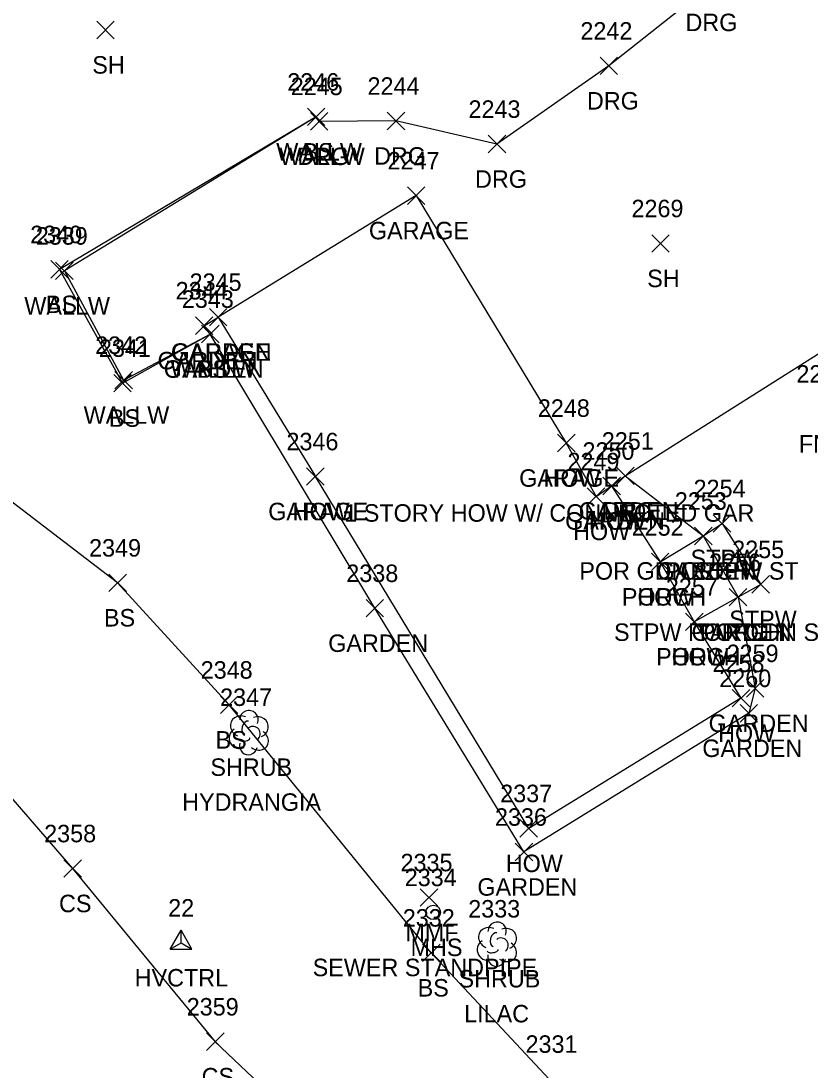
# Model space of a CAD drawing. Extents: x 1520648 to 1523413, y 732854 to 735518.
# Drawn here: x 1521973.9 to 1522064.2, y 733841.6 to 733961.6 of the extents above; entities that cross this region are included whole.
import ezdxf

# ---------------------------------------------------------------- set-up
doc = ezdxf.new("R2010")
doc.units = 0
for name, color, linetype in [('C_A', 7, 'Continuous'), ('C_I', 7, 'Continuous'), ('CPSM', 7, 'Continuous'), ('L_A', 7, 'Continuous'), ('L_C', 7, 'Continuous'), ('L_I', 7, 'Continuous'), ('L_TIC', 7, 'Continuous'), ('LAPB', 7, 'Continuous'), ('LBC', 7, 'Continuous'), ('LBF', 7, 'Continuous'), ('LELB', 7, 'Continuous'), ('LSH', 7, 'Continuous'), ('LW', 7, 'Continuous'), ('R_A', 7, 'Continuous'), ('R_I', 7, 'Continuous'), ('R_TIC', 7, 'Continuous'), ('RDG', 7, 'Continuous'), ('U_A', 7, 'Continuous'), ('U_I', 7, 'Continuous'), ('USMH', 7, 'Continuous')]:
    doc.layers.add(name, color=color, linetype=linetype)

msp = doc.modelspace()

# ---------------------------------------------------------------- linework, layer by layer
at = {"layer": 'CPSM'}
for p, q in [((1521990.97, 733855.4), (1521992.22, 733857.56)), ((1521993.47, 733855.4), (1521992.22, 733857.56)), ((1521992.22, 733856.12), (1521992.22, 733857.56)), ((1521990.97, 733855.4), (1521992.22, 733856.12)), ((1521990.97, 733855.4), (1521993.47, 733855.4)), ((1521992.22, 733856.12), (1521992.22, 733856.12)), ((1521992.22, 733856.12), (1521993.47, 733855.4))]:
    msp.add_line(p, q, dxfattribs=at)
at = {"layer": 'L_TIC'}
for points in [[(1521982.57, 733959.57), (1521984.57, 733961.57)], [(1521984.57, 733959.57), (1521982.57, 733961.57)], [(1522006.7, 733949.62), (1522008.7, 733951.62)], [(1522008.7, 733949.62), (1522006.7, 733951.62)], [(1522006.7, 733949.62), (1522008.7, 733951.62)], [(1522008.7, 733949.62), (1522006.7, 733951.62)], [(1522007.04, 733949.11), (1522009.04, 733951.11)], [(1522009.04, 733949.11), (1522007.04, 733951.11)], [(1522018.13, 733940.61), (1522020.13, 733942.61)], [(1522020.13, 733940.61), (1522018.13, 733942.61)], [(1522018.13, 733940.61), (1522020.13, 733942.61)], [(1522020.13, 733940.61), (1522018.13, 733942.61)], [(1522046.11, 733935.14), (1522048.11, 733937.14)], [(1522048.11, 733935.14), (1522046.11, 733937.14)], [(1521977.3, 733932.17), (1521979.3, 733934.17)], [(1521979.3, 733932.17), (1521977.3, 733934.17)], [(1521977.86, 733932), (1521979.86, 733934)], [(1521979.86, 733932), (1521977.86, 733934)], [(1521995.46, 733926.71), (1521997.46, 733928.71)], [(1521997.46, 733926.71), (1521995.46, 733928.71)], [(1521995.46, 733926.71), (1521997.46, 733928.71)], [(1521997.46, 733926.71), (1521995.46, 733928.71)], [(1521993.86, 733925.73), (1521995.86, 733927.73)], [(1521995.86, 733925.73), (1521993.86, 733927.73)], [(1521994.57, 733924.77), (1521996.57, 733926.77)], [(1521996.57, 733924.77), (1521994.57, 733926.77)], [(1521994.57, 733924.77), (1521996.57, 733926.77)], [(1521996.57, 733924.77), (1521994.57, 733926.77)], [(1521994.57, 733924.77), (1521996.57, 733926.77)], [(1521996.57, 733924.77), (1521994.57, 733926.77)], [(1521984.65, 733919.5), (1521986.65, 733921.5)], [(1521986.65, 733919.5), (1521984.65, 733921.5)], [(1521984.51, 733919.16), (1521986.51, 733921.16)], [(1521986.51, 733919.16), (1521984.51, 733921.16)], [(1522035.33, 733912.3), (1522037.33, 733914.3)], [(1522037.33, 733912.3), (1522035.33, 733914.3)], [(1522035.33, 733912.3), (1522037.33, 733914.3)], [(1522037.33, 733912.3), (1522035.33, 733914.3)], [(1522042.08, 733908.54), (1522044.08, 733910.54)], [(1522044.08, 733908.54), (1522042.08, 733910.54)], [(1522006.6, 733908.47), (1522008.6, 733910.47)], [(1522008.6, 733908.47), (1522006.6, 733910.47)], [(1522006.6, 733908.47), (1522008.6, 733910.47)], [(1522008.6, 733908.47), (1522006.6, 733910.47)], [(1522040.52, 733907.39), (1522042.52, 733909.39)], [(1522042.52, 733907.39), (1522040.52, 733909.39)], [(1522040.52, 733907.39), (1522042.52, 733909.39)], [(1522042.52, 733907.39), (1522040.52, 733909.39)], [(1522038.73, 733906.19), (1522040.73, 733908.19)], [(1522040.73, 733906.19), (1522038.73, 733908.19)], [(1522053.16, 733903.1), (1522055.16, 733905.1)], [(1522055.16, 733903.1), (1522053.16, 733905.1)], [(1522051.01, 733901.67), (1522053.01, 733903.67)], [(1522053.01, 733901.67), (1522051.01, 733903.67)], [(1522051.01, 733901.67), (1522053.01, 733903.67)], [(1522053.01, 733901.67), (1522051.01, 733903.67)], [(1522051.01, 733901.67), (1522053.01, 733903.67)], [(1522053.01, 733901.67), (1522051.01, 733903.67)], [(1522046.07, 733898.7), (1522048.07, 733900.7)], [(1522048.07, 733898.7), (1522046.07, 733900.7)], [(1522046.07, 733898.7), (1522048.07, 733900.7)], [(1522048.07, 733898.7), (1522046.07, 733900.7)], [(1521983.96, 733896.31), (1521985.96, 733898.31)], [(1521985.96, 733896.31), (1521983.96, 733898.31)], [(1522057.58, 733896.13), (1522059.58, 733898.13)], [(1522059.58, 733896.13), (1522057.58, 733898.13)], [(1522054.99, 733894.66), (1522056.99, 733896.66)], [(1522056.99, 733894.66), (1522054.99, 733896.66)], [(1522054.99, 733894.66), (1522056.99, 733896.66)], [(1522056.99, 733894.66), (1522054.99, 733896.66)], [(1522054.99, 733894.66), (1522056.99, 733896.66)], [(1522056.99, 733894.66), (1522054.99, 733896.66)], [(1522013.4, 733893.4), (1522015.4, 733895.4)], [(1522015.4, 733893.4), (1522013.4, 733895.4)], [(1522049.98, 733891.85), (1522051.98, 733893.85)], [(1522051.98, 733891.85), (1522049.98, 733893.85)], [(1522049.98, 733891.85), (1522051.98, 733893.85)], [(1522051.98, 733891.85), (1522049.98, 733893.85)], [(1522056.95, 733884.24), (1522058.95, 733886.24)], [(1522058.95, 733884.24), (1522056.95, 733886.24)], [(1521996.73, 733882.34), (1521998.73, 733884.34)], [(1521998.73, 733882.34), (1521996.73, 733884.34)], [(1522055.32, 733883.1), (1522057.32, 733885.1)], [(1522057.32, 733883.1), (1522055.32, 733885.1)], [(1522056.23, 733881.38), (1522058.23, 733883.38)], [(1522058.23, 733881.38), (1522056.23, 733883.38)], [(1522031.02, 733868.21), (1522033.02, 733870.21)], [(1522033.02, 733868.21), (1522031.02, 733870.21)], [(1522030.48, 733865.51), (1522032.48, 733867.51)], [(1522032.48, 733865.51), (1522030.48, 733867.51)], [(1521978.81, 733863.62), (1521980.81, 733865.62)], [(1521980.81, 733863.62), (1521978.81, 733865.62)], [(1522019.61, 733860.3), (1522021.61, 733862.3)], [(1522021.61, 733860.3), (1522019.61, 733862.3)], [(1522019.87, 733853.97), (1522021.87, 733855.97)], [(1522021.87, 733853.97), (1522019.87, 733855.97)], [(1521995.14, 733843.8), (1521997.14, 733845.8)], [(1521997.14, 733843.8), (1521995.14, 733845.8)]]:
    msp.add_lwpolyline(points, dxfattribs=at)
at = {"layer": 'LAPB'}
for points in [[(1522055.99, 733895.66), (1522057.95, 733885.24), (1522057.23, 733882.38), (1522031.48, 733866.51), (1522014.4, 733894.4), (1521995.57, 733925.77), (1521994.86, 733926.73), (1521996.46, 733927.71)], [(1522041.52, 733908.39), (1522043.08, 733909.54), (1522052.01, 733902.67)]]:
    msp.add_lwpolyline(points, dxfattribs=at)
at = {"layer": 'LBC'}
for points in [[(1522019.13, 733941.61), (1521996.46, 733927.71), (1522007.6, 733909.47)], [(1522019.13, 733941.61), (1522036.33, 733913.3)], [(1522036.33, 733913.3), (1522039.73, 733907.19), (1522041.52, 733908.39), (1522047.07, 733899.7), (1522050.98, 733892.85), (1522056.32, 733884.1), (1522032.02, 733869.21), (1522007.6, 733909.47)]]:
    msp.add_lwpolyline(points, dxfattribs=at)
at = {"layer": 'LBF'}
for points in [[(1522052.01, 733902.67), (1522054.16, 733904.1), (1522058.58, 733897.13), (1522055.99, 733895.66)], [(1522047.07, 733899.7), (1522052.01, 733902.67), (1522055.99, 733895.66), (1522050.98, 733892.85)]]:
    msp.add_lwpolyline(points, dxfattribs=at)
at = {"layer": 'LELB'}
for points in [[(1522007.7, 733950.62), (1521978.3, 733933.17), (1521985.51, 733920.16), (1521995.57, 733925.77)], [(1522038.26, 733821.74), (1522034.35, 733840.53), (1522020.87, 733854.97), (1521997.73, 733883.34), (1521984.96, 733897.31), (1521967.97, 733910.29), (1521948.34, 733926.34)], [(1521935.5, 733911.29), (1521950.9, 733894.84), (1521962.92, 733884.06), (1521979.81, 733864.62), (1521996.14, 733844.8), (1522019.29, 733822.84), (1522000.66, 733804.64), (1521971.81, 733783.01), (1521953.74, 733771.36), (1521896.07, 733749.17)]]:
    msp.add_lwpolyline(points, dxfattribs=at)
at = {"layer": 'LSH'}
for p, q in [((1521999.95, 733880.22), (1521999.95, 733880.22)), ((1521999.95, 733880.22), (1521999.95, 733880.22)), ((1522028.36, 733856.01), (1522028.36, 733856.01)), ((1522028.36, 733856.01), (1522028.36, 733856.01))]:
    msp.add_line(p, q, dxfattribs=at)
for centre in [(1522000, 733881.65), (1522028.41, 733857.44)]:
    msp.add_arc(centre, 1.05, 335.5272, 180.9563, dxfattribs=at)
for centre, major_axis, ratio, start_param, end_param in [((1521999.16, 733880.88), (1.21, -0.51), 0.895232, 1.570796, 4.712389), ((1522000.99, 733880.8), (-1.14, -0.48), 0.949671, 1.570796, 4.712389), ((1521998.87, 733879.51), (0.58, -1.04), 0.959034, 3.141593, 6.283185), ((1521999.74, 733880.68), (-0.208, -0.792), 0.645439, 3.141593, 6.283185), ((1522000.45, 733880.05), (-0.5, 0.667), 0.989748, 3.141593, 6.283185), ((1521999.49, 733879.47), (-0.625, -0.083), 0.423636, 0, 3.141593), ((1522000.95, 733879.38), (-1.09, 0.79), 0.841452, 1.570796, 4.712389), ((1521999.95, 733878.72), (0.26, 1.06), 0.942809, 1.570796, 4.712389), ((1522027.57, 733856.67), (1.21, -0.51), 0.895232, 1.570796, 4.712389), ((1522029.4, 733856.59), (-1.14, -0.48), 0.949671, 1.570796, 4.712389), ((1522028.15, 733856.47), (-0.208, -0.792), 0.645439, 3.141593, 6.283185), ((1522028.86, 733855.84), (-0.5, 0.667), 0.989748, 3.141593, 6.283185), ((1522027.28, 733855.3), (0.58, -1.04), 0.959034, 3.141593, 6.283185), ((1522027.9, 733855.26), (-0.625, -0.083), 0.423636, 0, 3.141593), ((1522029.36, 733855.17), (-1.09, 0.79), 0.841452, 1.570796, 4.712389), ((1522028.36, 733854.51), (0.26, 1.06), 0.942809, 1.570796, 4.712389)]:
    msp.add_ellipse(centre, major_axis=major_axis, ratio=ratio, start_param=start_param, end_param=end_param, dxfattribs=at)
at = {"layer": 'LW'}
msp.add_lwpolyline([(1522008.04, 733950.11), (1522007.7, 733950.62), (1521978.86, 733933), (1521985.65, 733920.5), (1521995.57, 733925.77)], dxfattribs=at)
at = {"layer": 'R_TIC'}
for points in [[(1522040.2, 733955.46), (1522042.2, 733957.46)], [(1522042.2, 733955.46), (1522040.2, 733957.46)], [(1522007.04, 733949.11), (1522009.04, 733951.11)], [(1522009.04, 733949.11), (1522007.04, 733951.11)], [(1522015.83, 733949.15), (1522017.83, 733951.15)], [(1522017.83, 733949.15), (1522015.83, 733951.15)], [(1522027.39, 733946.51), (1522029.39, 733948.51)], [(1522029.39, 733946.51), (1522027.39, 733948.51)], [(1522042.08, 733908.54), (1522044.08, 733910.54)], [(1522044.08, 733908.54), (1522042.08, 733910.54)]]:
    msp.add_lwpolyline(points, dxfattribs=at)
at = {"layer": 'RDG'}
for points in [[(1522064.05, 733973.67), (1522052.48, 733965.43), (1522041.2, 733956.46), (1522028.39, 733947.51), (1522016.83, 733950.15), (1522008.04, 733950.11)], [(1522043.08, 733909.54), (1522070.54, 733926.9), (1522079.21, 733926.11), (1522083.31, 733923.24), (1522097.82, 733907.52), (1522112.92, 733892.72), (1522129.47, 733872.78), (1522127.34, 733861.55)]]:
    msp.add_lwpolyline(points, dxfattribs=at)
at = {"layer": 'USMH'}
for p, q in [((1522021.09, 733859.6), (1522021.09, 733859.6)), ((1522021.92, 733859.6), (1522021.92, 733859.6))]:
    msp.add_line(p, q, dxfattribs=at)
msp.add_circle((1522021.09, 733859.6), 0.833, dxfattribs=at)

# ---------------------------------------------------------------- texts
at = {"layer": 'C_A'}
msp.add_text('HVCTRL', height=2, dxfattribs=at).set_placement((1521986.91, 733851.12))
at = {"layer": 'C_I'}
msp.add_text('22', height=2, dxfattribs=at).set_placement((1521990.75, 733859.12))
at = {"layer": 'L_A'}
for s, p in [('SH', (1521982.06, 733955.57)), ('WALLW', (1522003.12, 733945.62)), ('WALLW', (1522003.46, 733945.11)), ('BS', (1522006.14, 733945.62)), ('GARAGE', (1522013.73, 733936.61)), ('GARAGE', (1522013.73, 733936.61)), ('SH', (1522045.59, 733931.14)), ('WALLW', (1521974.28, 733928)), ('BS', (1521976.74, 733928.17)), ('GARDEN', (1521989.53, 733921.73)), ('GARAGE', (1521991.06, 733922.71)), ('GARDEN', (1521991.13, 733922.71)), ('GARDEN', (1521990.24, 733920.77)), ('WALLW', (1521990.99, 733920.77)), ('BS', (1521994.02, 733920.77)), ('WALLW', (1521981.07, 733915.5)), ('BS', (1521983.96, 733915.16)), ('FNR', (1522062.95, 733912.21)), ('GARAGE', (1522030.93, 733908.3)), ('HOW', (1522033.72, 733908.3)), ('GARAGE', (1522002.2, 733904.47)), ('HOW', (1522004.99, 733904.47)), ('GARDEN', (1522037.75, 733904.54)), ('GARDEN', (1522036.19, 733903.39)), ('HOW', (1522038.91, 733903.39)), ('HOW', (1522037.11, 733902.19)), ('STPW', (1522050.56, 733899.1)), ('POR GDN STPW ST', (1522037.82, 733897.67)), ('GARDEN', (1522046.68, 733897.67)), ('PORCH', (1522047.63, 733897.67)), ('PORCH', (1522042.69, 733894.7)), ('HOW', (1522044.45, 733894.7)), ('BS', (1521983.4, 733892.31)), ('STPW', (1522054.98, 733892.13)), ('STPW POR GDN ST', (1522041.79, 733890.66)), ('GARDEN', (1522050.66, 733890.66)), ('PORCH', (1522051.61, 733890.66)), ('GARDEN', (1522009.07, 733889.4)), ('PORCH', (1522046.61, 733887.85)), ('HOW', (1522048.37, 733887.85)), ('GARDEN', (1522052.62, 733880.24)), ('HOW', (1522053.71, 733879.1)), ('BS', (1521996.17, 733878.34)), ('GARDEN', (1522051.9, 733877.38)), ('SHRUB', (1521995.58, 733875.22)), ('HOW', (1522029.4, 733864.21)), ('GARDEN', (1522026.15, 733861.51)), ('CS', (1521978.25, 733859.62)), ('MMF', (1522017.9, 733856.3)), ('SHRUB', (1522023.99, 733851.01)), ('BS', (1522019.31, 733849.97)), ('CS', (1521994.58, 733839.8))]:
    msp.add_text(s, height=2, dxfattribs=at).set_placement(p)
at = {"layer": 'L_C'}
for s, p in [('1 STORY HOW W/ CONNECTED GAR', (1522010.91, 733904.3)), ('HYDRANGIA', (1521992.35, 733871.22)), ('SEWER STANDPIPE', (1522007.29, 733852.3)), ('LILAC', (1522024.63, 733847.01))]:
    msp.add_text(s, height=2, dxfattribs=at).set_placement(p)
at = {"layer": 'L_I'}
for s, p in [('2246', (1522004.38, 733953.62)), ('2246', (1522004.38, 733953.62)), ('2245', (1522004.78, 733953.11)), ('2247', (1522015.87, 733944.61)), ('2247', (1522015.87, 733944.61)), ('2269', (1522043.79, 733939.14)), ('2340', (1521974.95, 733936.17)), ('2339', (1521975.59, 733936)), ('2345', (1521993.2, 733930.71)), ('2345', (1521993.2, 733930.71)), ('2344', (1521991.6, 733929.73)), ('2343', (1521992.31, 733928.77)), ('2343', (1521992.31, 733928.77)), ('2343', (1521992.31, 733928.77)), ('2342', (1521982.39, 733923.5)), ('2341', (1521982.82, 733923.16)), ('2261', (1522062.67, 733920.21)), ('2248', (1522033.07, 733916.3)), ('2248', (1522033.07, 733916.3)), ('2346', (1522004.29, 733912.47)), ('2346', (1522004.29, 733912.47)), ('2251', (1522040.39, 733912.54)), ('2250', (1522038.18, 733911.39)), ('2250', (1522038.18, 733911.39)), ('2249', (1522036.46, 733910.19)), ('2254', (1522050.9, 733907.1)), ('2253', (1522048.75, 733905.67)), ('2253', (1522048.75, 733905.67)), ('2253', (1522048.75, 733905.67)), ('2252', (1522043.81, 733902.7)), ('2252', (1522043.81, 733902.7)), ('2349', (1521981.69, 733900.31)), ('2255', (1522055.32, 733900.13)), ('2256', (1522052.67, 733898.66)), ('2256', (1522052.67, 733898.66)), ('2256', (1522052.67, 733898.66)), ('2338', (1522011.14, 733897.4)), ('2257', (1522047.72, 733895.85)), ('2257', (1522047.72, 733895.85)), ('2259', (1522054.68, 733888.24)), ('2258', (1522053.06, 733887.1)), ('2348', (1521994.47, 733886.34)), ('2260', (1522053.84, 733885.38)), ('2347', (1521996.69, 733883.22)), ('2337', (1522028.76, 733872.21)), ('2336', (1522028.16, 733869.51)), ('2358', (1521976.55, 733867.62)), ('2335', (1522017.35, 733864.3)), ('2333', (1522025.1, 733859.01)), ('2332', (1522017.61, 733857.97)), ('2359', (1521992.87, 733847.8)), ('2331', (1522031.66, 733843.53))]:
    msp.add_text(s, height=2, dxfattribs=at).set_placement(p)
at = {"layer": 'R_A'}
for p in [(1522049.97, 733960.43), (1522038.69, 733951.46), (1522005.53, 733945.11), (1522014.32, 733945.15), (1522025.88, 733942.51), (1522040.57, 733904.54)]:
    msp.add_text('DRG', height=2, dxfattribs=at).set_placement(p)
at = {"layer": 'R_I'}
for s, p in [('2242', (1522037.94, 733959.46)), ('2245', (1522004.78, 733953.11)), ('2244', (1522013.57, 733953.15)), ('2243', (1522025.13, 733950.51)), ('2251', (1522040.39, 733912.54))]:
    msp.add_text(s, height=2, dxfattribs=at).set_placement(p)
at = {"layer": 'U_A'}
msp.add_text('MHS', height=2, dxfattribs=at).set_placement((1522018.5, 733854.6))
at = {"layer": 'U_I'}
msp.add_text('2334', height=2, dxfattribs=at).set_placement((1522017.83, 733862.6))

doc.saveas('drawing.dxf')
